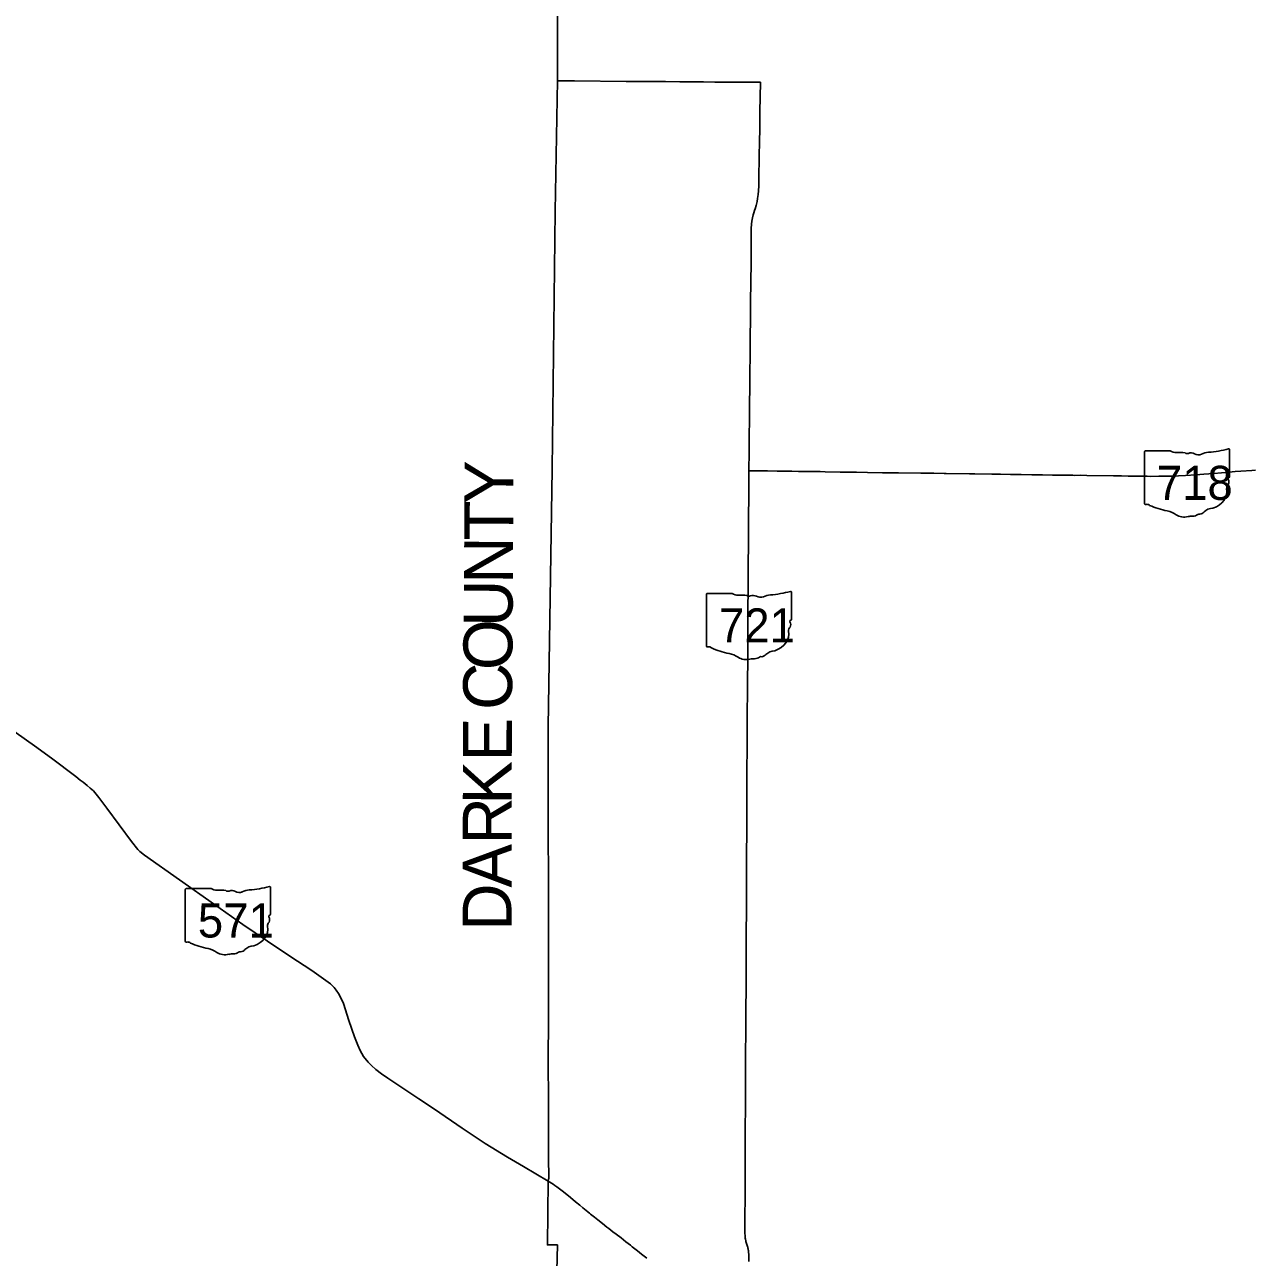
# Model space of a CAD drawing. Extents: x 0 to 34, y 0 to 22.
# Drawn here: x 4.0908 to 4.4953, y 16.6359 to 17.0413 of the extents above; entities that cross this region are included whole.
import ezdxf

# ---------------------------------------------------------------- set-up
doc = ezdxf.new("R2010")
doc.units = 0
for name, color, linetype in [('GM_X_County', 7, 'Continuous'), ('GM_X_County_Text', 7, 'Continuous'), ('GM_X_State_Location', 7, 'Continuous'), ('GM_X_State_Route', 7, 'Continuous'), ('GM_X_State_Shield', 7, 'Continuous')]:
    doc.layers.add(name, color=color, linetype=linetype)

msp = doc.modelspace()

# ---------------------------------------------------------------- linework, layer by layer
at = {"layer": 'GM_X_County'}
for points in [[(4.26488, 16.59763), (4.26592, 16.64002), (4.26264, 16.64004), (4.26291, 16.66108), (4.26301, 16.66151), (4.26304, 16.66168), (4.26307, 16.6619), (4.26308, 16.66208), (4.26308, 16.6625), (4.26307, 16.66322), (4.26303, 16.66769), (4.26302, 16.66979), (4.26301, 16.67086), (4.26299, 16.67312), (4.26298, 16.67554), (4.26297, 16.67719), (4.26296, 16.67928), (4.26296, 16.6808), (4.26296, 16.68391), (4.26297, 16.68553), (4.26297, 16.68799), (4.26297, 16.6915), (4.26294, 16.69629), (4.26292, 16.70039), (4.26292, 16.70215), (4.26291, 16.70317), (4.26291, 16.70435), (4.2629, 16.70537), (4.26295, 16.70963), (4.26296, 16.7121), (4.26297, 16.71421), (4.26297, 16.7164), (4.26298, 16.7185), (4.26298, 16.72043), (4.263, 16.72341), (4.26301, 16.72412), (4.26302, 16.72578), (4.26291, 16.81041), (4.26421, 16.8951), (4.26523, 16.97998), (4.26591, 17.02288), (4.26594, 17.06507)], [(4.26594, 17.06507), (4.26591, 17.02288), (4.26523, 16.97998), (4.26421, 16.8951), (4.26291, 16.81041), (4.26302, 16.72578), (4.26301, 16.72412), (4.263, 16.72341), (4.26298, 16.72043), (4.26298, 16.7185), (4.26297, 16.7164), (4.26297, 16.71421), (4.26296, 16.7121), (4.26295, 16.70963), (4.2629, 16.70537), (4.26291, 16.70435), (4.26291, 16.70317), (4.26292, 16.70215), (4.26292, 16.70039), (4.26294, 16.69629), (4.26297, 16.6915), (4.26297, 16.68799), (4.26297, 16.68553), (4.26296, 16.68391), (4.26296, 16.6808), (4.26296, 16.67928), (4.26297, 16.67719), (4.26298, 16.67554), (4.26299, 16.67312), (4.26301, 16.67086), (4.26302, 16.66979), (4.26303, 16.66769), (4.26307, 16.66322), (4.26308, 16.6625), (4.26308, 16.66208), (4.26307, 16.6619), (4.26304, 16.66168), (4.26301, 16.66151), (4.26291, 16.66108), (4.26264, 16.64004), (4.26592, 16.64002), (4.26488, 16.59763)]]:
    msp.add_lwpolyline(points, dxfattribs=at)
at = {"layer": 'GM_X_State_Route'}
for points in [[(4.26593, 17.02284), (4.26596, 17.06503), (4.26702, 17.13824), (4.26698, 17.15055)], [(4.30141, 17.02256), (4.30132, 17.02256), (4.28858, 17.02264), (4.2715, 17.0228), (4.26593, 17.02284)], [(4.33017, 17.02233), (4.32815, 17.02233), (4.32215, 17.02239), (4.31766, 17.02242), (4.31397, 17.02247), (4.31302, 17.02249), (4.31229, 17.02247), (4.31118, 17.02246), (4.30976, 17.02248), (4.30617, 17.02252), (4.30141, 17.02256)], [(4.32907, 16.91427), (4.3291, 16.91723), (4.32915, 16.92134), (4.32918, 16.92387), (4.32918, 16.92519), (4.32918, 16.92835), (4.32925, 16.93099), (4.32928, 16.93262), (4.32929, 16.93468), (4.32932, 16.93657), (4.32933, 16.9381), (4.3294, 16.94501), (4.32943, 16.94781), (4.32953, 16.95888), (4.32956, 16.96072), (4.32957, 16.9631), (4.32957, 16.96689), (4.32959, 16.9699), (4.32964, 16.97428), (4.3297, 16.97569), (4.3298, 16.97668), (4.33, 16.97771), (4.33027, 16.97878), (4.33049, 16.97946), (4.3307, 16.98013), (4.3309, 16.98077), (4.33122, 16.98186), (4.33153, 16.98309), (4.33173, 16.98413), (4.33194, 16.98549), (4.33205, 16.98659), (4.33207, 16.98715), (4.3321, 16.98772), (4.33213, 16.98858), (4.33218, 16.99124), (4.33236, 17.00357), (4.33242, 17.00626), (4.33244, 17.01069), (4.33244, 17.01127), (4.33247, 17.01259), (4.33265, 17.02235), (4.33095, 17.02233), (4.33017, 17.02233)], [(4.3284, 16.63947), (4.32837, 16.63955), (4.32816, 16.64018), (4.32805, 16.64052), (4.32795, 16.64083), (4.32788, 16.6411), (4.3278, 16.64142), (4.32772, 16.64187), (4.32767, 16.64224), (4.32762, 16.64272), (4.32759, 16.64319), (4.32757, 16.64364), (4.32755, 16.64511), (4.32757, 16.6507), (4.32759, 16.65418), (4.32759, 16.65692), (4.3276, 16.65918), (4.32761, 16.66093), (4.32761, 16.66287), (4.32762, 16.66482), (4.32765, 16.6694), (4.32766, 16.67099), (4.32765, 16.67367), (4.32766, 16.67895), (4.32769, 16.6847), (4.32771, 16.6906), (4.32776, 16.69719), (4.32779, 16.70405), (4.32782, 16.7089), (4.32783, 16.71201), (4.32785, 16.71665), (4.32792, 16.72537), (4.32794, 16.72799), (4.32794, 16.73052), (4.32796, 16.73421), (4.32798, 16.73917), (4.328, 16.74455), (4.32802, 16.74818), (4.32804, 16.75267), (4.32806, 16.75667), (4.32808, 16.76189), (4.32809, 16.76659), (4.32814, 16.77787), (4.32818, 16.78388), (4.32819, 16.78473), (4.32819, 16.78552), (4.32819, 16.78604), (4.3282, 16.78694), (4.32822, 16.79427), (4.32823, 16.79696), (4.32826, 16.80249), (4.32827, 16.80587), (4.3283, 16.80999), (4.3283, 16.81561), (4.32836, 16.82109), (4.32838, 16.82441), (4.32849, 16.83333), (4.32851, 16.84466), (4.32856, 16.85073), (4.32859, 16.85389), (4.32866, 16.86191), (4.32867, 16.86491), (4.32872, 16.86934), (4.32871, 16.87214), (4.32877, 16.88068), (4.3288, 16.88495), (4.32882, 16.8888), (4.32887, 16.89459), (4.32888, 16.89582), (4.32891, 16.89967), (4.32894, 16.90156), (4.32897, 16.90568), (4.32904, 16.91174), (4.32907, 16.91427)], [(4.32887, 16.89459), (4.32946, 16.89458), (4.3302, 16.89458), (4.3324, 16.89455), (4.33495, 16.89452), (4.33816, 16.89447), (4.34106, 16.89444), (4.34301, 16.89441), (4.34512, 16.8944), (4.35224, 16.8943), (4.35393, 16.89426), (4.35883, 16.89418), (4.36178, 16.89412), (4.36426, 16.89411), (4.36785, 16.89404), (4.37275, 16.89395), (4.3756, 16.8939), (4.37808, 16.89388), (4.38535, 16.89381), (4.38968, 16.89375), (4.39307, 16.89371), (4.39374, 16.8937), (4.40138, 16.89358), (4.40307, 16.89354), (4.40866, 16.89347), (4.41151, 16.89345), (4.41483, 16.8934), (4.41831, 16.89333), (4.42189, 16.89329), (4.42537, 16.89322), (4.42864, 16.89317), (4.4336, 16.89313), (4.43537, 16.89309), (4.43597, 16.89307), (4.43776, 16.89309), (4.43992, 16.89306), (4.44873, 16.89292), (4.45131, 16.8929), (4.45352, 16.89284), (4.45666, 16.8928), (4.45716, 16.89279), (4.45786, 16.89278), (4.45859, 16.89277), (4.45978, 16.89276)], [(4.45978, 16.89276), (4.4608, 16.89275), (4.4636, 16.89276), (4.4644, 16.89278), (4.46528, 16.8928), (4.46586, 16.8928), (4.46644, 16.8928), (4.46694, 16.89281), (4.46755, 16.89282), (4.46812, 16.89285), (4.47008, 16.89293), (4.4723, 16.89303), (4.47572, 16.89322), (4.4784, 16.89344), (4.48171, 16.89373), (4.48423, 16.89394), (4.48561, 16.89405), (4.48649, 16.89412), (4.48765, 16.89422), (4.4887, 16.8943), (4.49049, 16.89445), (4.49411, 16.89468), (4.49532, 16.89474)], [(4.07298, 16.81879), (4.0791, 16.81461), (4.0846, 16.81087), (4.09406, 16.80415), (4.09965, 16.80004), (4.10761, 16.79404), (4.10913, 16.79288)], [(4.10913, 16.79288), (4.1101, 16.79215), (4.11139, 16.79113), (4.11242, 16.79027), (4.11343, 16.78932), (4.11521, 16.78718), (4.11783, 16.78364), (4.12591, 16.77273), (4.12801, 16.77004), (4.12869, 16.76942), (4.13026, 16.76814), (4.15328, 16.75199), (4.16256, 16.74539), (4.17062, 16.73995), (4.17794, 16.73499), (4.18519, 16.73022), (4.18833, 16.72807), (4.19131, 16.72588), (4.19252, 16.72467), (4.1932, 16.72376), (4.19395, 16.72275), (4.19487, 16.7211), (4.19559, 16.71941), (4.19741, 16.71386), (4.19922, 16.70846), (4.20029, 16.70575), (4.20105, 16.70393), (4.20217, 16.70197), (4.20371, 16.70014), (4.20479, 16.69898), (4.2063, 16.69768), (4.2081, 16.69633), (4.21025, 16.69487), (4.2204, 16.68807), (4.22551, 16.68462), (4.23465, 16.67846), (4.23628, 16.67731), (4.2399, 16.67487), (4.24224, 16.67333), (4.24954, 16.66892), (4.25474, 16.66586), (4.26293, 16.66104)], [(4.26293, 16.66104), (4.26451, 16.65999), (4.26507, 16.6596), (4.26573, 16.65912), (4.26662, 16.65848), (4.26796, 16.65743), (4.27018, 16.65563), (4.2719, 16.65423), (4.27327, 16.65311), (4.27433, 16.65224), (4.27598, 16.65089), (4.27608, 16.65081), (4.27646, 16.6505), (4.27684, 16.65019), (4.27815, 16.64912), (4.27919, 16.64829), (4.28077, 16.64702), (4.28218, 16.64589), (4.28284, 16.64538), (4.28346, 16.6449), (4.28417, 16.64436), (4.28522, 16.64355), (4.28683, 16.6423), (4.28839, 16.64109), (4.28992, 16.63989)], [(4.28992, 16.63989), (4.29051, 16.63943), (4.29227, 16.63804), (4.29355, 16.63702), (4.29528, 16.63565)], [(4.32881, 16.63458), (4.32882, 16.63598), (4.32882, 16.63648), (4.32881, 16.63695), (4.32876, 16.63755), (4.32873, 16.63786), (4.32869, 16.63822), (4.32866, 16.6384), (4.32862, 16.63861), (4.32858, 16.63879), (4.32854, 16.63897), (4.32849, 16.63916), (4.32846, 16.63928), (4.3284, 16.63947)]]:
    msp.add_lwpolyline(points, dxfattribs=at)
at = {"layer": 'GM_X_State_Shield'}
for p, q in [((4.45888, 16.90082), (4.45888, 16.88383)), ((4.46735, 16.90111), (4.45916, 16.90111)), ((4.48686, 16.89265), (4.48686, 16.90153)), ((4.48685, 16.89265), (4.48686, 16.89265)), ((4.34286, 16.84575), (4.34286, 16.85464)), ((4.31489, 16.85393), (4.31489, 16.83694)), ((4.32335, 16.85422), (4.31516, 16.85422)), ((4.34286, 16.84576), (4.34286, 16.84575)), ((4.15211, 16.75719), (4.14392, 16.75719)), ((4.17161, 16.74872), (4.17161, 16.75761)), ((4.14364, 16.7569), (4.14364, 16.73991)), ((4.17161, 16.74873), (4.17161, 16.74872))]:
    msp.add_line(p, q, dxfattribs=at)
for centre, major_axis, start_param, end_param in [((4.4592, 16.90085), (0.000324, 0), 1.712693, 3.28349), ((4.4693, 16.90308), (0.00314, 0), 4.042523, 4.731795), ((4.47034, 16.89157), (0.01128, 0), 1.404758, 1.657858), ((4.4729, 16.90094), (0.000907, 0), 3.836095, 5.185415), ((4.47424, 16.89898), (0.00189, 0), 0.950623, 2.079405), ((4.47667, 16.90167), (0.00227, 0), 4.081561, 5.145723), ((4.48067, 16.89592), (0.00597, 0), 1.699011, 2.107814), ((4.47689, 16.92426), (0.02966, 0), 4.814394, 5.042369), ((4.48654, 16.90157), (0.000311, 0), 6.141152, 7.989035), ((4.48678, 16.89199), (0.000482, 0), 1.883978, 3.671073), ((4.48372, 16.89087), (0.00289, 0), 5.934695, 6.695948), ((4.48652, 16.89261), (0.000333, 0), 5.05454, 6.418171), ((4.47855, 16.8878), (0.00742, 0), 5.101752, 6.440018), ((4.48797, 16.88893), (0.0021, 0), 2.387724, 3.262537), ((4.45921, 16.8838), (0.000327, 0), 3.00124, 4.508301), ((4.45926, 16.88553), (0.00249, 0), 4.665946, 4.897461), ((4.45977, 16.88285), (0.0009, 0), 0.519207, 1.627899), ((4.47112, 16.89811), (0.02142, 0), 4.195997, 4.488961), ((4.46474, 16.8762), (0.0067, 0), 0.823519, 1.323587), ((4.47199, 16.88277), (0.00425, 0), 4.026481, 4.996735), ((4.47444, 16.8769), (0.00349, 0), 1.495662, 1.94098), ((4.47475, 16.8815), (0.00227, 0), 4.691044, 5.507374), ((4.4768, 16.87985), (0.000638, 0), 1.147584, 2.315152), ((4.47653, 16.88219), (0.0024, 0), 4.937069, 5.64225), ((4.48168, 16.87906), (0.00406, 0), 1.647645, 2.488434), ((4.33289, 16.87737), (0.02966, 0), 4.814394, 5.042369), ((4.34255, 16.85468), (0.000311, 0), 6.141152, 7.989035), ((4.31521, 16.85396), (0.000324, 0), 1.712693, 3.28349), ((4.3253, 16.85619), (0.00314, 0), 4.042523, 4.731795), ((4.32635, 16.84468), (0.01128, 0), 1.404758, 1.657858), ((4.32891, 16.85405), (0.000907, 0), 3.836095, 5.185415), ((4.33024, 16.85209), (0.00189, 0), 0.950623, 2.079405), ((4.33267, 16.85478), (0.00227, 0), 4.081561, 5.145723), ((4.33668, 16.84903), (0.00597, 0), 1.699011, 2.107814), ((4.34397, 16.84204), (0.0021, 0), 2.387724, 3.262537), ((4.34279, 16.8451), (0.000482, 0), 1.883978, 3.671073), ((4.33972, 16.84398), (0.00289, 0), 5.934695, 6.695948), ((4.34253, 16.84572), (0.000333, 0), 5.05454, 6.418171), ((4.33456, 16.84091), (0.00742, 0), 5.101752, 6.440018), ((4.31521, 16.8369), (0.000327, 0), 3.00124, 4.508301), ((4.31526, 16.83864), (0.00249, 0), 4.665946, 4.897461), ((4.31577, 16.83596), (0.0009, 0), 0.519207, 1.627899), ((4.32713, 16.85122), (0.02142, 0), 4.195997, 4.488961), ((4.32074, 16.82931), (0.0067, 0), 0.823519, 1.323587), ((4.33768, 16.83217), (0.00406, 0), 1.647645, 2.488434), ((4.32799, 16.83588), (0.00425, 0), 4.026481, 4.996735), ((4.33045, 16.83001), (0.00349, 0), 1.495662, 1.94098), ((4.33076, 16.83461), (0.00227, 0), 4.691044, 5.507374), ((4.33281, 16.83296), (0.000638, 0), 1.147584, 2.315152), ((4.33254, 16.8353), (0.0024, 0), 4.937069, 5.64225), ((4.14396, 16.75693), (0.000324, 0), 1.712693, 3.28349), ((4.15406, 16.75916), (0.00314, 0), 4.042523, 4.731795), ((4.16165, 16.78034), (0.02966, 0), 4.814394, 5.042369), ((4.1713, 16.75765), (0.000311, 0), 6.141152, 7.989035), ((4.1551, 16.74765), (0.01128, 0), 1.404758, 1.657858), ((4.15766, 16.75702), (0.000907, 0), 3.836095, 5.185415), ((4.15899, 16.75506), (0.00189, 0), 0.950623, 2.079405), ((4.16143, 16.75775), (0.00227, 0), 4.081561, 5.145723), ((4.16543, 16.752), (0.00597, 0), 1.699011, 2.107814), ((4.17273, 16.74501), (0.0021, 0), 2.387724, 3.262537), ((4.17154, 16.74807), (0.000482, 0), 1.883978, 3.671073), ((4.16847, 16.74695), (0.00289, 0), 5.934695, 6.695948), ((4.17128, 16.74869), (0.000333, 0), 5.05454, 6.418171), ((4.16331, 16.74388), (0.00742, 0), 5.101752, 6.440018), ((4.14396, 16.73987), (0.000327, 0), 3.00124, 4.508301), ((4.14401, 16.74161), (0.00249, 0), 4.665946, 4.897461), ((4.14452, 16.73893), (0.0009, 0), 0.519207, 1.627899), ((4.15588, 16.75419), (0.02142, 0), 4.195997, 4.488961), ((4.14949, 16.73228), (0.0067, 0), 0.823519, 1.323587), ((4.16129, 16.73827), (0.0024, 0), 4.937069, 5.64225), ((4.16644, 16.73514), (0.00406, 0), 1.647645, 2.488434), ((4.15674, 16.73885), (0.00425, 0), 4.026481, 4.996735), ((4.1592, 16.73297), (0.00349, 0), 1.495662, 1.94098), ((4.15951, 16.73758), (0.00227, 0), 4.691044, 5.507374), ((4.16156, 16.73593), (0.000638, 0), 1.147584, 2.315152)]:
    msp.add_ellipse(centre, major_axis=major_axis, ratio=0.8, start_param=start_param, end_param=end_param, dxfattribs=at)

# ---------------------------------------------------------------- texts
at = {"layer": 'GM_X_County_Text'}
for s, rotation, p in [('Y', 89.6173, (4.25144, 16.88357)), ('T', 89.6173, (4.25136, 16.87157)), ('N', 89.617, (4.25127, 16.85738)), ('U', 89.6176, (4.25117, 16.84319)), ('O', 89.6203, (4.25108, 16.829)), ('C', 89.6732, (4.251, 16.8159)), ('E', 89.801, (4.25094, 16.799)), ('K', 89.8932, (4.25091, 16.78482)), ('R', 89.918, (4.25089, 16.77172)), ('A', 89.9184, (4.25087, 16.75753)), ('D', 89.9183, (4.25085, 16.74334))]:
    msp.add_text(s, height=0.01607, rotation=rotation, dxfattribs=at).set_placement(p)
at = {"layer": 'GM_X_State_Location'}
for s, p in [('s', (4.47255, 16.8912)), ('r', (4.47255, 16.8912)), ('s', (4.32856, 16.8443)), ('r', (4.32856, 16.8443)), ('s', (4.15731, 16.74727)), ('r', (4.15731, 16.74727))]:
    msp.add_text(s, height=0.0000161, dxfattribs=at).set_placement(p)
for s, p in [('718', (4.46688, 16.89003)), ('721', (4.32288, 16.84314)), ('571', (4.15164, 16.7461))]:
    msp.add_text(s, height=0.0000161, rotation=0, dxfattribs=at).set_placement(p)
at = {"layer": 'GM_X_State_Shield'}
for s, p in [('718', (4.46292, 16.88503)), ('721', (4.31901, 16.83814)), ('571', (4.14776, 16.74111))]:
    msp.add_text(s, height=0.011189, dxfattribs=at).set_placement(p)

doc.saveas('drawing.dxf')
